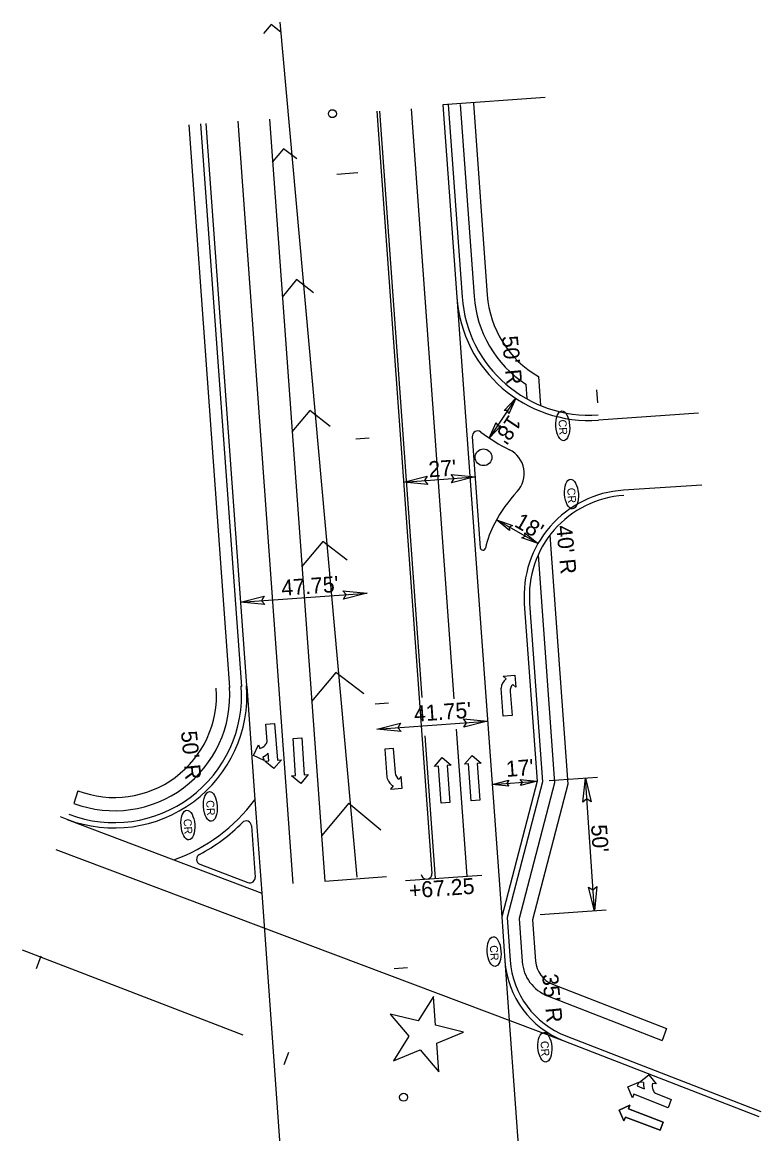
# Model space of a CAD drawing. Extents: x 2131049 to 2132623, y 643184 to 644993.
# Drawn here: x 2132300 to 2132578.1, y 643713 to 644131.6 of the extents above; entities that cross this region are included whole.
import ezdxf

# ---------------------------------------------------------------- set-up
doc = ezdxf.new("R2010")
doc.units = 0
for name, color, linetype in [('Prop Conc 2ft 6in Curb and Gutter', 7, 'Continuous'), ('Prop Conc 4in Sidewalk', 7, 'Continuous'), ('Prop Conc 5in Monolithic Keyed In Island', 7, 'Continuous'), ('Prop Dimension Text', 7, 'Continuous'), ('Prop DSN Text', 7, 'Continuous'), ('Prop EOT', 7, 'Continuous'), ('Prop Horizontal Alignment Station Label', 7, 'Continuous'), ('Prop Horizontal Alignment Tick Large', 7, 'Continuous'), ('Prop Horizontal Alignment Tick Small', 7, 'Continuous'), ('Prop Lane Arrow CELL', 7, 'Continuous'), ('Prop Lane Lines', 7, 'Continuous'), ('Prop Paint Stripe', 7, 'Continuous'), ('Prop RDY Traffic Signal CELL', 7, 'Continuous'), ('Prop Terminator CELL', 7, 'Continuous'), ('Prop WCC CELL', 7, 'Continuous'), ('Scratch_Level_3', 7, 'Continuous')]:
    doc.layers.add(name, color=color, linetype=linetype)

msp = doc.modelspace()

# ---------------------------------------------------------------- linework, layer by layer
at = {"layer": 'Prop Conc 2ft 6in Curb and Gutter'}
for p, q in [((2132460.39, 644100.66), (2132465.64, 644028.18)), ((2132367.18, 644093.3), (2132382.52, 643881.49)), ((2132491.05, 643912.73), (2132495.91, 643845.58)), ((2132495.91, 643845.58), (2132482.56, 643794.53)), ((2132482.56, 643794.53), (2132483.74, 643778.3)), ((2132504.72, 643749.92), (2132578.08, 643721.46))]:
    msp.add_line(p, q, dxfattribs=at)
for centre, radius, start, end in [((2132513.51, 644031.65), 48, 184.1431, 274.0466), ((2132528.95, 643915.48), 38, 93.7357, 184.1431), ((2132334.63, 643878.21), 48, 249.1873, 4.1431), ((2132516.65, 643780.69), 33, 184.1431, 248.7931)]:
    msp.add_arc(centre, radius, start, end, dxfattribs=at)
at = {"layer": 'Prop Conc 4in Sidewalk'}
for p, q in [((2132469.88, 644101.11), (2132475.11, 644028.87)), ((2132464.9, 644100.7), (2132470.13, 644028.51)), ((2132362.69, 644092.98), (2132378.03, 643881.16)), ((2132494.38, 643998.24), (2132495.17, 643987.29)), ((2132489.58, 643995.33), (2132489.97, 643989.82)), ((2132516.23, 643993.24), (2132516.58, 643988.26)), ((2132498.71, 643938.48), (2132505.5, 643844.7)), ((2132494.24, 643930.95), (2132500.45, 643845.17)), ((2132321, 643842.2), (2132319.43, 643837.45)), ((2132500.45, 643845.17), (2132487.11, 643794.12)), ((2132505.5, 643844.7), (2132492.15, 643793.65)), ((2132487.11, 643794.12), (2132488.28, 643777.86)), ((2132492.15, 643793.65), (2132493.29, 643778.02)), ((2132499.64, 643769.42), (2132542.65, 643752.74)), ((2132497.82, 643764.96), (2132540.98, 643748.21)), ((2132542.65, 643752.74), (2132540.98, 643748.21))]:
    msp.add_line(p, q, dxfattribs=at)
for centre, radius, start, end in [((2132513.51, 644031.65), 43.5, 184.1431, 236.6117), ((2132513.51, 644031.65), 38.5, 184.1431, 240.195), ((2132334.68, 643878.19), 43.5, 249.482, 3.9517), ((2132334.68, 643878.19), 38.5, 249.1873, 3.9517), ((2132503.24, 643778.95), 15, 184.1431, 248.7931), ((2132503.26, 643778.75), 10, 184.1431, 248.7931)]:
    msp.add_arc(centre, radius, start, end, dxfattribs=at)
at = {"layer": 'Prop Conc 5in Monolithic Keyed In Island'}
for p, q in [((2132433.5, 644098.11), (2132454.29, 643811.11)), ((2132469.45, 643975.55), (2132472.48, 643933.73)), ((2132386.32, 643828.99), (2132387.72, 643809.72)), ((2132366.94, 643814.57), (2132385.01, 643807.71)), ((2132452.41, 643808.97), (2132452.31, 643808.97))]:
    msp.add_line(p, q, dxfattribs=at)
for centre, radius, start, end in [((2132471.45, 643975.7), 2, 53.0607, 184.1431), ((2132513.51, 644031.65), 68, 233.0607, 243.7794), ((2132479.05, 643961.67), 10, 317.2031, 63.7794), ((2132528.95, 643915.48), 58, 137.2031, 151.6326), ((2132508.71, 643926.4), 35, 151.6326, 168.1363), ((2132473.48, 643933.8), 1, 184.1431, 348.1363), ((2132334.68, 643878.19), 68, 298.105, 315.1794), ((2132384.33, 643828.85), 2, 4.1431, 135.1794), ((2132367.65, 643816.44), 2, 118.105, 249.1873), ((2132385.72, 643809.57), 2, 249.1873, 4.1431), ((2132452.19, 643810.97), 2, 187.1277, 273.2769), ((2132452.3, 643810.97), 2, 273.2769, 4.0465)]:
    msp.add_arc(centre, radius, start, end, dxfattribs=at)
at = {"layer": 'Prop Dimension Text'}
for p, q in [((2132496.9, 644103.3), (2132458.39, 644100.51)), ((2132476.93, 643844.63), (2132493.89, 643845.77)), ((2132498.38, 643846.07), (2132516.56, 643847.3)), ((2132515.44, 643797.04), (2132512.07, 643847)), ((2132444.35, 643808.43), (2132473.08, 643810.37)), ((2132495.08, 643795.66), (2132519.93, 643797.34))]:
    msp.add_line(p, q, dxfattribs=at)
at = {"layer": 'Prop DSN Text'}
for p, q in [((2132485.81, 643990.02), (2132475.84, 643975.04)), ((2132443.62, 643958.43), (2132470.55, 643960.38)), ((2132494.22, 643935.33), (2132478.6, 643944.27)), ((2132382.23, 643913.21), (2132429.85, 643916.66)), ((2132433.57, 643865.36), (2132475.21, 643868.38))]:
    msp.add_line(p, q, dxfattribs=at)
at = {"layer": 'Prop EOT'}
for p, q in [((2132458.39, 644100.51), (2132463.64, 644028.04)), ((2132369.17, 644093.45), (2132384.5, 643881.82)), ((2132554.61, 643984.43), (2132517.04, 643981.77)), ((2132555.92, 643957.32), (2132526.34, 643955.39)), ((2132489.05, 643912.59), (2132493.89, 643845.77)), ((2132493.89, 643845.77), (2132480.54, 643794.68)), ((2132480.54, 643794.68), (2132481.73, 643778.16)), ((2132503.99, 643748.06), (2132577.36, 643719.59))]:
    msp.add_line(p, q, dxfattribs=at)
for centre, radius, start, end in [((2132513.51, 644031.65), 50, 184.1431, 274.0466), ((2132528.95, 643915.48), 40, 93.7357, 184.1431), ((2132334.63, 643878.21), 50, 249.1873, 4.1431), ((2132516.65, 643780.69), 35, 184.1431, 248.7931)]:
    msp.add_arc(centre, radius, start, end, dxfattribs=at)
at = {"layer": 'Prop Horizontal Alignment Station Label'}
for p, q in [((2132307.07, 643779.87), (2132305.25, 643775.21)), ((2132400.28, 643743.65), (2132398.47, 643738.99))]:
    msp.add_line(p, q, dxfattribs=at)
for centre in [(2132416.78, 644097.19), (2132443.6, 643726.82)]:
    msp.add_circle(centre, 1.5, dxfattribs=at)
at = {"layer": 'Prop Horizontal Alignment Tick Large'}
msp.add_line((2132418.42, 644074.46), (2132426.4, 644075.04), dxfattribs=at)
at = {"layer": 'Prop Horizontal Alignment Tick Small'}
for p, q in [((2132425.65, 643974.72), (2132430.63, 643975.09)), ((2132432.87, 643874.99), (2132437.86, 643875.35)), ((2132440.1, 643775.25), (2132445.08, 643775.61))]:
    msp.add_line(p, q, dxfattribs=at)
at = {"layer": 'Prop Lane Arrow CELL'}
for p, q in [((2132391.69, 643867.24), (2132394.98, 643867.52)), ((2132392.24, 643860.81), (2132391.69, 643867.24)), ((2132394.98, 643867.52), (2132396.16, 643853.77)), ((2132387.13, 643855.51), (2132388.99, 643859.53)), ((2132388.99, 643859.53), (2132389.51, 643858.17)), ((2132401.97, 643861.93), (2132405.26, 643862.16)), ((2132402.94, 643847.97), (2132401.97, 643861.93)), ((2132405.26, 643862.16), (2132406.23, 643848.19)), ((2132391.15, 643853.64), (2132387.13, 643855.51)), ((2132390.63, 643855.05), (2132391.15, 643853.64)), ((2132392.87, 643853.49), (2132392.63, 643856.33)), ((2132439.86, 643858.08), (2132436.58, 643857.85)), ((2132436.58, 643857.85), (2132437.32, 643847.38)), ((2132440.5, 643848.92), (2132439.86, 643858.08)), ((2132455.24, 643851.37), (2132458.12, 643854.71)), ((2132458.12, 643854.71), (2132461.46, 643851.83)), ((2132466.57, 643852.2), (2132469.45, 643855.53)), ((2132469.45, 643855.53), (2132472.79, 643852.65)), ((2132391.38, 643853.36), (2132392.87, 643853.49)), ((2132394.78, 643850.54), (2132391.38, 643853.36)), ((2132397.65, 643853.9), (2132394.78, 643850.54)), ((2132396.16, 643853.77), (2132397.65, 643853.9)), ((2132456.71, 643851.48), (2132455.24, 643851.37)), ((2132457.73, 643837.58), (2132456.71, 643851.48)), ((2132461.46, 643851.83), (2132459.99, 643851.72)), ((2132459.99, 643851.72), (2132461, 643837.81)), ((2132468.04, 643852.3), (2132466.57, 643852.2)), ((2132469.06, 643838.4), (2132468.04, 643852.3)), ((2132472.79, 643852.65), (2132471.32, 643852.54)), ((2132471.32, 643852.54), (2132472.33, 643838.64)), ((2132401.45, 643847.86), (2132402.94, 643847.97)), ((2132404.86, 643844.94), (2132401.45, 643847.86)), ((2132407.73, 643848.3), (2132404.86, 643844.94)), ((2132406.23, 643848.19), (2132407.73, 643848.3)), ((2132442.73, 643847.6), (2132441.82, 643846.55)), ((2132443.04, 643843.18), (2132442.73, 643847.6)), ((2132439.69, 643844.1), (2132438.62, 643842.87)), ((2132438.62, 643842.87), (2132443.04, 643843.18)), ((2132461, 643837.81), (2132457.73, 643837.58)), ((2132472.33, 643838.64), (2132469.06, 643838.4)), ((2132528.81, 643723.84), (2132524.73, 643721.97)), ((2132524.73, 643721.97), (2132526.57, 643717.95)), ((2132528.28, 643722.44), (2132528.81, 643723.84)), ((2132541.36, 643717.46), (2132528.28, 643722.44)), ((2132526.57, 643717.95), (2132527.11, 643719.35)), ((2132527.11, 643719.35), (2132540.19, 643714.38)), ((2132540.19, 643714.38), (2132541.36, 643717.46))]:
    msp.add_line(p, q, dxfattribs=at)
for centre, radius, start, end in [((2132388.24, 643862.42), 4.43, 286.6021, 317.4557), ((2132389.76, 643861.24), 2.52, 313.9656, 350.2776), ((2132389.37, 643859.32), 4.43, 286.4833, 317.3619), ((2132442.4, 643848.46), 5.22, 192.6936, 238.0053), ((2132443.73, 643849.15), 3.26, 184.0175, 233.6757)]:
    msp.add_arc(centre, radius, start, end, dxfattribs=at)
at = {"layer": 'Prop Lane Lines'}
for p, q in [((2132434.5, 644098.18), (2132450.5, 643877.29)), ((2132446.47, 644099.05), (2132462.57, 643876.79)), ((2132381.14, 644094.31), (2132401.93, 643807.35)), ((2132463.64, 644028.04), (2132480.55, 643794.68)), ((2132384.52, 643881.63), (2132387.61, 643838.85)), ((2132451.54, 643862.95), (2132455.44, 643809.17)), ((2132463.4, 643865.36), (2132467.4, 643810.04)), ((2132387.61, 643838.85), (2132390.17, 643803.61)), ((2132314.27, 643832.46), (2132316.87, 643831.47)), ((2132316.91, 643831.45), (2132357.14, 643816.16)), ((2132312.63, 643820.09), (2132503.99, 643748.06)), ((2132357.14, 643816.16), (2132390.17, 643803.61)), ((2132390.17, 643803.61), (2132400.62, 643659.29)), ((2132300.02, 643782.37), (2132383.05, 643750.31)), ((2132300.02, 643782.37), (2132383.05, 643750.31)), ((2132481.73, 643778.16), (2132495.01, 643595.09))]:
    msp.add_line(p, q, dxfattribs=at)
msp.add_arc((2132334.63, 643878.21), 66, 289.9363, 323.394, dxfattribs=at)
at = {"layer": 'Prop Paint Stripe'}
for p, q in [((2132396.98, 644131.62), (2132425.97, 643809.63)), ((2132393.11, 644095.18), (2132413.9, 643808.22)), ((2132422.95, 643837.5), (2132412.67, 643825.18)), ((2132422.95, 643837.5), (2132423, 643837.5)), ((2132423, 643837.5), (2132435.01, 643827.47)), ((2132413.9, 643808.22), (2132437.21, 643809.91))]:
    msp.add_line(p, q, dxfattribs=at)
for points in [[(2132397.44, 644127.93), (2132393.7, 644130.82), (2132390.86, 644127.42)], [(2132403.41, 644080.15), (2132398.44, 644084), (2132394.18, 644078.9)], [(2132409.71, 644029.78), (2132403.34, 644034.7), (2132397.86, 644028.13)], [(2132416.01, 643979.41), (2132408.25, 643985.4), (2132401.54, 643977.36)], [(2132422.31, 643929.03), (2132413.15, 643936.1), (2132405.21, 643926.59)], [(2132428.61, 643878.66), (2132418.06, 643886.81), (2132408.89, 643875.83)]]:
    msp.add_lwpolyline(points, dxfattribs=at)
at = {"layer": 'Prop RDY Traffic Signal CELL'}
msp.add_lwpolyline([(2132455.62, 643753.92), (2132454.83, 643764.78), (2132449.09, 643755.53), (2132438.51, 643758.14), (2132445.54, 643749.81), (2132439.79, 643740.55), (2132449.88, 643744.66), (2132456.9, 643736.33), (2132456.11, 643747.2), (2132466.21, 643751.31), (2132455.62, 643753.92)], dxfattribs=at)
at = {"layer": 'Prop Terminator CELL'}
for p, q in [((2132481.07, 643885.37), (2132485.46, 643885.74)), ((2132482.2, 643884.4), (2132481.07, 643885.37)), ((2132485.46, 643885.74), (2132485.84, 643881.26)), ((2132481.12, 643870.28), (2132480.35, 643880.81)), ((2132483.75, 643879.65), (2132484.42, 643870.52)), ((2132485.84, 643881.26), (2132484.71, 643882.23)), ((2132484.42, 643870.52), (2132481.12, 643870.28)), ((2132532.48, 643732.52), (2132535.95, 643735.28)), ((2132535.95, 643735.28), (2132538.71, 643731.81)), ((2132528.08, 643730.67), (2132532.13, 643732.44)), ((2132529.79, 643726.59), (2132528.08, 643730.67)), ((2132532.13, 643732.44), (2132531.57, 643731.05)), ((2132531.57, 643731.05), (2132534.22, 643729.99)), ((2132533.98, 643732.35), (2132532.48, 643732.52)), ((2132538.71, 643731.81), (2132537.26, 643731.95)), ((2132530.35, 643727.98), (2132529.79, 643726.59)), ((2132543.17, 643722.87), (2132530.35, 643727.98)), ((2132538.4, 643728.33), (2132544.39, 643725.93)), ((2132544.39, 643725.93), (2132543.17, 643722.87)), ((2132524.73, 643721.97), (2132528.81, 643723.84)), ((2132526.57, 643717.95), (2132524.73, 643721.97)), ((2132528.81, 643723.84), (2132528.28, 643722.44)), ((2132528.28, 643722.44), (2132541.36, 643717.46)), ((2132527.11, 643719.35), (2132526.57, 643717.95)), ((2132540.19, 643714.38), (2132527.11, 643719.35)), ((2132541.36, 643717.46), (2132540.19, 643714.38))]:
    msp.add_line(p, q, dxfattribs=at)
for points in [[(2132481.42, 643985.38), (2132485.81, 643990.02), (2132483.24, 643984.13), (2132482.75, 643985.42)], [(2132480.24, 643979.68), (2132475.84, 643975.04), (2132478.42, 643980.93), (2132478.91, 643979.64)], [(2132452.71, 643957.54), (2132443.62, 643958.43), (2132452.53, 643960.68), (2132451.5, 643959)], [(2132461.46, 643961.28), (2132470.55, 643960.38), (2132461.64, 643958.13), (2132462.67, 643959.81)], [(2132483.53, 643940.2), (2132478.6, 643944.27), (2132484.65, 643942.1), (2132483.4, 643941.52)], [(2132489.29, 643939.4), (2132494.22, 643935.33), (2132488.17, 643937.5), (2132489.42, 643938.08)], [(2132420.77, 643917.55), (2132429.85, 643916.66), (2132420.94, 643914.41), (2132421.97, 643916.08)], [(2132391.32, 643912.31), (2132382.23, 643913.21), (2132391.14, 643915.46), (2132390.11, 643913.78)], [(2132442.66, 643864.47), (2132433.57, 643865.36), (2132442.48, 643867.61), (2132441.45, 643865.94)], [(2132466.12, 643869.28), (2132475.21, 643868.38), (2132466.3, 643866.13), (2132467.33, 643867.81)], [(2132483.29, 643843.97), (2132476.93, 643844.63), (2132483.18, 643846.17), (2132482.45, 643845)], [(2132487.53, 643846.43), (2132493.89, 643845.77), (2132487.65, 643844.23), (2132488.37, 643845.4)], [(2132511.13, 643837.91), (2132512.07, 643847), (2132514.28, 643838.08), (2132512.6, 643839.12)], [(2132516.38, 643806.12), (2132515.44, 643797.04), (2132513.24, 643805.96), (2132514.91, 643804.92)]]:
    msp.add_lwpolyline(points, close=True, dxfattribs=at)
for centre, radius, start, end in [((2132485.57, 643880.39), 5.25, 130.2012, 175.5129), ((2132487, 643879.9), 3.27, 134.5308, 184.1889), ((2132538.35, 643731.57), 4.43, 169.8334, 200.712), ((2132541.63, 643731.18), 4.43, 169.9522, 200.8058), ((2132539.9, 643730.36), 2.52, 197.3157, 233.6277)]:
    msp.add_arc(centre, radius, start, end, dxfattribs=at)
at = {"layer": 'Prop WCC CELL'}
for centre in [(2132503.53, 643979.64), (2132506.81, 643953.95), (2132370.85, 643836.3), (2132362.38, 643829.29), (2132477.69, 643781.68), (2132496.78, 643745.65)]:
    msp.add_ellipse(centre, major_axis=(0.38, -5.59), ratio=0.462467, dxfattribs=at)
at = {"layer": 'Scratch_Level_3'}
msp.add_circle((2132473.69, 643967.79), 3.15, dxfattribs=at)

# ---------------------------------------------------------------- texts
at = {"layer": 'Prop Dimension Text'}
msp.add_text('+67.25', height=6, rotation=4.1585, dxfattribs=at).set_placement((2132445.8, 643801.67))
at = {"layer": 'Prop DSN Text'}
for s, rotation, p in [("50' R", 275.472, (2132480.58, 644013.3)), ("18'", 236.3576, (2132483.38, 643984.2)), ("27'", 4.1431, (2132453.2, 643960.23)), ("18'", 330.2358, (2132484.92, 643941.98)), ("40' R", 275.472, (2132501.02, 643941.91)), ("47.75'", 4.1431, (2132397.79, 643915.57)), ("41.75'", 4.1431, (2132447.72, 643868.18)), ("50' R", 275.472, (2132359.77, 643864.52)), ("17'", 4.1431, (2132482.35, 643847.43)), ("50'", 273.8612, (2132514.16, 643829.3)), ("35' R", 275.472, (2132495.75, 643773.01))]:
    msp.add_text(s, height=6, rotation=rotation, dxfattribs=at).set_placement(p)
at = {"layer": 'Prop WCC CELL'}
for p in [(2132501.9, 643981.89), (2132505.18, 643956.2), (2132369.22, 643838.55), (2132360.74, 643831.54), (2132476.05, 643783.93), (2132495.15, 643747.9)]:
    msp.add_text('CR', height=3, rotation=273.8612, dxfattribs=at).set_placement(p)

doc.saveas('drawing.dxf')
